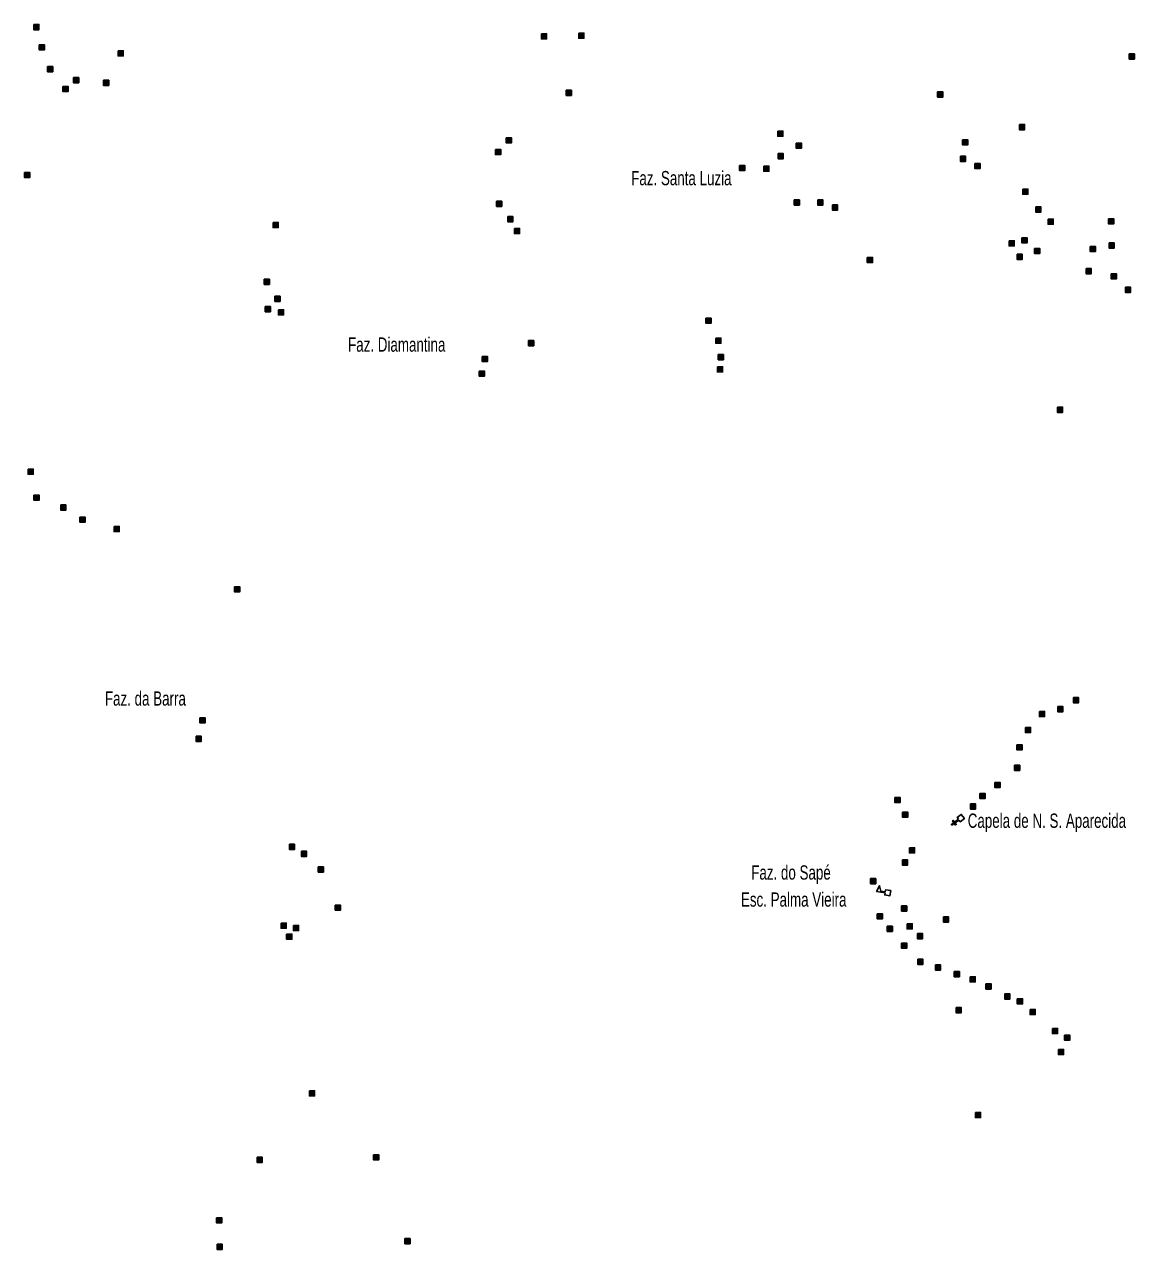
# Model space of a CAD drawing. Extents: x 265.7 to 292.1, y 7676.2 to 7704.2.
# Drawn here: x 279.63 to 285.84, y 7683.29 to 7690.15 of the extents above; entities that cross this region are included whole.
import ezdxf

# ---------------------------------------------------------------- set-up
doc = ezdxf.new("R2010")
doc.units = 0
doc.header["$LTSCALE"] = 0.032
for name, color, linetype, lineweight in [('2', 7, 'Continuous', 25), ('4', 7, 'Continuous', 25), ('6', 7, 'Continuous', 25)]:
    doc.layers.add(name, color=color, linetype=linetype, lineweight=lineweight)
doc.layers.add('61', color=7, linetype='Continuous')

msp = doc.modelspace()

# ---------------------------------------------------------------- hatches: boundary and pattern name
at = {"layer": '2'}
for points in [[(279.6791, 7690.1472), (279.7081, 7690.1472), (279.7081, 7690.1182), (279.6791, 7690.1182)], [(282.5223, 7690.0956), (282.5513, 7690.0956), (282.5513, 7690.0666), (282.5223, 7690.0666)], [(282.7314, 7690.0988), (282.7604, 7690.0988), (282.7604, 7690.0698), (282.7314, 7690.0698)], [(279.71, 7690.0341), (279.739, 7690.0341), (279.739, 7690.0051), (279.71, 7690.0051)], [(280.1511, 7690.0003), (280.1801, 7690.0003), (280.1801, 7689.9713), (280.1511, 7689.9713)], [(285.8142, 7689.9826), (285.8432, 7689.9826), (285.8432, 7689.9536), (285.8142, 7689.9536)], [(279.7565, 7689.9116), (279.7855, 7689.9116), (279.7855, 7689.8826), (279.7565, 7689.8826)], [(279.9019, 7689.8502), (279.9309, 7689.8502), (279.9309, 7689.8212), (279.9019, 7689.8212)], [(280.0698, 7689.8349), (280.0988, 7689.8349), (280.0988, 7689.8059), (280.0698, 7689.8059)], [(279.8429, 7689.8002), (279.8719, 7689.8002), (279.8719, 7689.7712), (279.8429, 7689.7712)], [(282.6612, 7689.7793), (282.6902, 7689.7793), (282.6902, 7689.7503), (282.6612, 7689.7503)], [(284.741, 7689.7695), (284.77, 7689.7695), (284.77, 7689.7405), (284.741, 7689.7405)], [(283.8451, 7689.5501), (283.8741, 7689.5501), (283.8741, 7689.5211), (283.8451, 7689.5211)], [(285.1986, 7689.5871), (285.2276, 7689.5871), (285.2276, 7689.5581), (285.1986, 7689.5581)], [(282.3247, 7689.5129), (282.3537, 7689.5129), (282.3537, 7689.4839), (282.3247, 7689.4839)], [(283.9493, 7689.483), (283.9783, 7689.483), (283.9783, 7689.454), (283.9493, 7689.454)], [(284.8807, 7689.5016), (284.9097, 7689.5016), (284.9097, 7689.4726), (284.8807, 7689.4726)], [(282.2649, 7689.4475), (282.2939, 7689.4475), (282.2939, 7689.4185), (282.2649, 7689.4185)], [(283.8476, 7689.4242), (283.8766, 7689.4242), (283.8766, 7689.3952), (283.8476, 7689.3952)], [(284.8684, 7689.4095), (284.8974, 7689.4095), (284.8974, 7689.3805), (284.8684, 7689.3805)], [(283.6321, 7689.3579), (283.6611, 7689.3579), (283.6611, 7689.3289), (283.6321, 7689.3289)], [(283.7668, 7689.3539), (283.7958, 7689.3539), (283.7958, 7689.3249), (283.7668, 7689.3249)], [(284.95, 7689.3692), (284.979, 7689.3692), (284.979, 7689.3402), (284.95, 7689.3402)], [(279.6275, 7689.3184), (279.6565, 7689.3184), (279.6565, 7689.2894), (279.6275, 7689.2894)], [(285.2172, 7689.2256), (285.2462, 7689.2256), (285.2462, 7689.1966), (285.2172, 7689.1966)], [(282.2714, 7689.1571), (282.3004, 7689.1571), (282.3004, 7689.1281), (282.2714, 7689.1281)], [(283.938, 7689.165), (283.967, 7689.165), (283.967, 7689.136), (283.938, 7689.136)], [(284.0694, 7689.1643), (284.0984, 7689.1643), (284.0984, 7689.1353), (284.0694, 7689.1353)], [(284.1518, 7689.1368), (284.1808, 7689.1368), (284.1808, 7689.1078), (284.1518, 7689.1078)], [(282.3335, 7689.0713), (282.3625, 7689.0713), (282.3625, 7689.0423), (282.3335, 7689.0423)], [(285.2905, 7689.1256), (285.3195, 7689.1256), (285.3195, 7689.0966), (285.2905, 7689.0966)], [(281.0197, 7689.0383), (281.0487, 7689.0383), (281.0487, 7689.0093), (281.0197, 7689.0093)], [(282.3705, 7689.0052), (282.3995, 7689.0052), (282.3995, 7688.9762), (282.3705, 7688.9762)], [(285.3591, 7689.0569), (285.3881, 7689.0569), (285.3881, 7689.0279), (285.3591, 7689.0279)], [(285.6982, 7689.0593), (285.7272, 7689.0593), (285.7272, 7689.0303), (285.6982, 7689.0303)], [(285.1412, 7688.9359), (285.1702, 7688.9359), (285.1702, 7688.9069), (285.1412, 7688.9069)], [(285.213, 7688.9528), (285.242, 7688.9528), (285.242, 7688.9238), (285.213, 7688.9238)], [(285.1855, 7688.8607), (285.2145, 7688.8607), (285.2145, 7688.8317), (285.1855, 7688.8317)], [(285.2833, 7688.893), (285.3123, 7688.893), (285.3123, 7688.864), (285.2833, 7688.864)], [(285.5956, 7688.9043), (285.6246, 7688.9043), (285.6246, 7688.8753), (285.5956, 7688.8753)], [(285.7013, 7688.9237), (285.7303, 7688.9237), (285.7303, 7688.8947), (285.7013, 7688.8947)], [(284.3471, 7688.843), (284.3761, 7688.843), (284.3761, 7688.814), (284.3471, 7688.814)], [(285.5721, 7688.7801), (285.6011, 7688.7801), (285.6011, 7688.7511), (285.5721, 7688.7511)], [(285.7126, 7688.751), (285.7416, 7688.751), (285.7416, 7688.722), (285.7126, 7688.722)], [(280.9697, 7688.7204), (280.9987, 7688.7204), (280.9987, 7688.6914), (280.9697, 7688.6914)], [(285.7926, 7688.6751), (285.8216, 7688.6751), (285.8216, 7688.6461), (285.7926, 7688.6461)], [(281.0294, 7688.6251), (281.0584, 7688.6251), (281.0584, 7688.5961), (281.0294, 7688.5961)], [(280.9752, 7688.567), (281.0042, 7688.567), (281.0042, 7688.538), (280.9752, 7688.538)], [(281.0496, 7688.5492), (281.0786, 7688.5492), (281.0786, 7688.5202), (281.0496, 7688.5202)], [(283.4431, 7688.5024), (283.4721, 7688.5024), (283.4721, 7688.4734), (283.4431, 7688.4734)], [(283.498, 7688.3911), (283.527, 7688.3911), (283.527, 7688.3621), (283.498, 7688.3621)], [(282.4505, 7688.3765), (282.4795, 7688.3765), (282.4795, 7688.3475), (282.4505, 7688.3475)], [(282.1907, 7688.2878), (282.2197, 7688.2878), (282.2197, 7688.2588), (282.1907, 7688.2588)], [(283.5126, 7688.2982), (283.5416, 7688.2982), (283.5416, 7688.2692), (283.5126, 7688.2692)], [(282.1737, 7688.2062), (282.2027, 7688.2062), (282.2027, 7688.1772), (282.1737, 7688.1772)], [(283.5078, 7688.2305), (283.5368, 7688.2305), (283.5368, 7688.2015), (283.5078, 7688.2015)], [(285.4116, 7688.0038), (285.4406, 7688.0038), (285.4406, 7687.9748), (285.4116, 7687.9748)], [(279.6476, 7687.6574), (279.6766, 7687.6574), (279.6766, 7687.6284), (279.6476, 7687.6284)], [(279.68, 7687.5114), (279.709, 7687.5114), (279.709, 7687.4824), (279.68, 7687.4824)], [(279.8308, 7687.4565), (279.8598, 7687.4565), (279.8598, 7687.4275), (279.8308, 7687.4275)], [(279.9374, 7687.3879), (279.9664, 7687.3879), (279.9664, 7687.3589), (279.9374, 7687.3589)], [(280.1295, 7687.3355), (280.1585, 7687.3355), (280.1585, 7687.3065), (280.1295, 7687.3065)], [(280.8042, 7686.998), (280.8332, 7686.998), (280.8332, 7686.969), (280.8042, 7686.969)], [(285.4132, 7686.3266), (285.4422, 7686.3266), (285.4422, 7686.2976), (285.4132, 7686.2976)], [(285.5012, 7686.3775), (285.5302, 7686.3775), (285.5302, 7686.3485), (285.5012, 7686.3485)], [(280.6096, 7686.2646), (280.6386, 7686.2646), (280.6386, 7686.2356), (280.6096, 7686.2356)], [(285.3107, 7686.3), (285.3397, 7686.3), (285.3397, 7686.271), (285.3107, 7686.271)], [(285.2325, 7686.2104), (285.2615, 7686.2104), (285.2615, 7686.1814), (285.2325, 7686.1814)], [(280.5879, 7686.1604), (280.6169, 7686.1604), (280.6169, 7686.1314), (280.5879, 7686.1314)], [(285.1848, 7686.1128), (285.2138, 7686.1128), (285.2138, 7686.0838), (285.1848, 7686.0838)], [(285.1719, 7685.9981), (285.2009, 7685.9981), (285.2009, 7685.9691), (285.1719, 7685.9691)], [(285.0614, 7685.9021), (285.0904, 7685.9021), (285.0904, 7685.8731), (285.0614, 7685.8731)], [(284.502, 7685.8181), (284.531, 7685.8181), (284.531, 7685.7891), (284.502, 7685.7891)], [(284.9241, 7685.7818), (284.9531, 7685.7818), (284.9531, 7685.7528), (284.9241, 7685.7528)], [(284.9774, 7685.84), (285.0064, 7685.84), (285.0064, 7685.811), (284.9774, 7685.811)], [(284.5448, 7685.7359), (284.5738, 7685.7359), (284.5738, 7685.7069), (284.5448, 7685.7069)], [(281.1109, 7685.5559), (281.1399, 7685.5559), (281.1399, 7685.5269), (281.1109, 7685.5269)], [(281.1778, 7685.5163), (281.2068, 7685.5163), (281.2068, 7685.4873), (281.1778, 7685.4873)], [(284.5827, 7685.5357), (284.6117, 7685.5357), (284.6117, 7685.5067), (284.5827, 7685.5067)], [(284.5432, 7685.4679), (284.5722, 7685.4679), (284.5722, 7685.4389), (284.5432, 7685.4389)], [(281.2723, 7685.4284), (281.3013, 7685.4284), (281.3013, 7685.3994), (281.2723, 7685.3994)], [(284.3657, 7685.363), (284.3947, 7685.363), (284.3947, 7685.334), (284.3657, 7685.334)], [(281.3675, 7685.2145), (281.3965, 7685.2145), (281.3965, 7685.1855), (281.3675, 7685.1855)], [(284.4028, 7685.166), (284.4318, 7685.166), (284.4318, 7685.137), (284.4028, 7685.137)], [(284.5392, 7685.2105), (284.5682, 7685.2105), (284.5682, 7685.1815), (284.5392, 7685.1815)], [(281.064, 7685.1144), (281.093, 7685.1144), (281.093, 7685.0854), (281.064, 7685.0854)], [(281.1334, 7685.1007), (281.1624, 7685.1007), (281.1624, 7685.0717), (281.1334, 7685.0717)], [(284.4585, 7685.0967), (284.4875, 7685.0967), (284.4875, 7685.0677), (284.4585, 7685.0677)], [(284.5698, 7685.1104), (284.5988, 7685.1104), (284.5988, 7685.0814), (284.5698, 7685.0814)], [(284.7732, 7685.1484), (284.8022, 7685.1484), (284.8022, 7685.1194), (284.7732, 7685.1194)], [(281.0955, 7685.0523), (281.1245, 7685.0523), (281.1245, 7685.0233), (281.0955, 7685.0233)], [(284.6279, 7685.0555), (284.6569, 7685.0555), (284.6569, 7685.0265), (284.6279, 7685.0265)], [(284.5392, 7685.0023), (284.5682, 7685.0023), (284.5682, 7684.9733), (284.5392, 7684.9733)], [(284.6296, 7684.9111), (284.6586, 7684.9111), (284.6586, 7684.8821), (284.6296, 7684.8821)], [(284.7281, 7684.8796), (284.7571, 7684.8796), (284.7571, 7684.8506), (284.7281, 7684.8506)], [(284.8337, 7684.8424), (284.8627, 7684.8424), (284.8627, 7684.8134), (284.8337, 7684.8134)], [(284.9226, 7684.8135), (284.9516, 7684.8135), (284.9516, 7684.7845), (284.9226, 7684.7845)], [(285.0113, 7684.7738), (285.0403, 7684.7738), (285.0403, 7684.7448), (285.0113, 7684.7448)], [(285.117, 7684.7174), (285.146, 7684.7174), (285.146, 7684.6884), (285.117, 7684.6884)], [(285.1871, 7684.69), (285.2161, 7684.69), (285.2161, 7684.661), (285.1871, 7684.661)], [(284.8442, 7684.6407), (284.8732, 7684.6407), (284.8732, 7684.6117), (284.8442, 7684.6117)], [(285.2583, 7684.6302), (285.2873, 7684.6302), (285.2873, 7684.6012), (285.2583, 7684.6012)], [(285.3833, 7684.5238), (285.4123, 7684.5238), (285.4123, 7684.4948), (285.3833, 7684.4948)], [(285.452, 7684.4866), (285.481, 7684.4866), (285.481, 7684.4576), (285.452, 7684.4576)], [(285.4172, 7684.4066), (285.4462, 7684.4066), (285.4462, 7684.3776), (285.4172, 7684.3776)], [(281.2229, 7684.1751), (281.2519, 7684.1751), (281.2519, 7684.1461), (281.2229, 7684.1461)], [(284.9523, 7684.0539), (284.9813, 7684.0539), (284.9813, 7684.0249), (284.9523, 7684.0249)], [(280.9301, 7683.8022), (280.9591, 7683.8022), (280.9591, 7683.7732), (280.9301, 7683.7732)], [(281.5822, 7683.8167), (281.6112, 7683.8167), (281.6112, 7683.7877), (281.5822, 7683.7877)], [(280.7034, 7683.4633), (280.7324, 7683.4633), (280.7324, 7683.4343), (280.7034, 7683.4343)], [(280.7057, 7683.3147), (280.7347, 7683.3147), (280.7347, 7683.2857), (280.7057, 7683.2857)], [(281.7581, 7683.3471), (281.7871, 7683.3471), (281.7871, 7683.3181), (281.7581, 7683.3181)]]:
    msp.add_hatch(color=256, dxfattribs=at).paths.add_polyline_path(points)

# ---------------------------------------------------------------- linework, layer by layer
for points in [[(279.6791, 7690.1472), (279.7081, 7690.1472), (279.7081, 7690.1182), (279.6791, 7690.1182)], [(282.5223, 7690.0956), (282.5513, 7690.0956), (282.5513, 7690.0666), (282.5223, 7690.0666)], [(282.7314, 7690.0988), (282.7604, 7690.0988), (282.7604, 7690.0698), (282.7314, 7690.0698)], [(279.71, 7690.0341), (279.739, 7690.0341), (279.739, 7690.0051), (279.71, 7690.0051)], [(280.1511, 7690.0003), (280.1801, 7690.0003), (280.1801, 7689.9713), (280.1511, 7689.9713)], [(285.8142, 7689.9826), (285.8432, 7689.9826), (285.8432, 7689.9536), (285.8142, 7689.9536)], [(279.7565, 7689.9116), (279.7855, 7689.9116), (279.7855, 7689.8826), (279.7565, 7689.8826)], [(279.9019, 7689.8502), (279.9309, 7689.8502), (279.9309, 7689.8212), (279.9019, 7689.8212)], [(280.0698, 7689.8349), (280.0988, 7689.8349), (280.0988, 7689.8059), (280.0698, 7689.8059)], [(279.8429, 7689.8002), (279.8719, 7689.8002), (279.8719, 7689.7712), (279.8429, 7689.7712)], [(282.6612, 7689.7793), (282.6902, 7689.7793), (282.6902, 7689.7503), (282.6612, 7689.7503)], [(284.741, 7689.7695), (284.77, 7689.7695), (284.77, 7689.7405), (284.741, 7689.7405)], [(283.8451, 7689.5501), (283.8741, 7689.5501), (283.8741, 7689.5211), (283.8451, 7689.5211)], [(285.1986, 7689.5871), (285.2276, 7689.5871), (285.2276, 7689.5581), (285.1986, 7689.5581)], [(282.3247, 7689.5129), (282.3537, 7689.5129), (282.3537, 7689.4839), (282.3247, 7689.4839)], [(283.9493, 7689.483), (283.9783, 7689.483), (283.9783, 7689.454), (283.9493, 7689.454)], [(284.8807, 7689.5016), (284.9097, 7689.5016), (284.9097, 7689.4726), (284.8807, 7689.4726)], [(282.2649, 7689.4475), (282.2939, 7689.4475), (282.2939, 7689.4185), (282.2649, 7689.4185)], [(283.8476, 7689.4242), (283.8766, 7689.4242), (283.8766, 7689.3952), (283.8476, 7689.3952)], [(284.8684, 7689.4095), (284.8974, 7689.4095), (284.8974, 7689.3805), (284.8684, 7689.3805)], [(283.6321, 7689.3579), (283.6611, 7689.3579), (283.6611, 7689.3289), (283.6321, 7689.3289)], [(283.7668, 7689.3539), (283.7958, 7689.3539), (283.7958, 7689.3249), (283.7668, 7689.3249)], [(284.95, 7689.3692), (284.979, 7689.3692), (284.979, 7689.3402), (284.95, 7689.3402)], [(279.6275, 7689.3184), (279.6565, 7689.3184), (279.6565, 7689.2894), (279.6275, 7689.2894)], [(285.2172, 7689.2256), (285.2462, 7689.2256), (285.2462, 7689.1966), (285.2172, 7689.1966)], [(282.2714, 7689.1571), (282.3004, 7689.1571), (282.3004, 7689.1281), (282.2714, 7689.1281)], [(283.938, 7689.165), (283.967, 7689.165), (283.967, 7689.136), (283.938, 7689.136)], [(284.0694, 7689.1643), (284.0984, 7689.1643), (284.0984, 7689.1353), (284.0694, 7689.1353)], [(284.1518, 7689.1368), (284.1808, 7689.1368), (284.1808, 7689.1078), (284.1518, 7689.1078)], [(282.3335, 7689.0713), (282.3625, 7689.0713), (282.3625, 7689.0423), (282.3335, 7689.0423)], [(285.2905, 7689.1256), (285.3195, 7689.1256), (285.3195, 7689.0966), (285.2905, 7689.0966)], [(281.0197, 7689.0383), (281.0487, 7689.0383), (281.0487, 7689.0093), (281.0197, 7689.0093)], [(282.3705, 7689.0052), (282.3995, 7689.0052), (282.3995, 7688.9762), (282.3705, 7688.9762)], [(285.3591, 7689.0569), (285.3881, 7689.0569), (285.3881, 7689.0279), (285.3591, 7689.0279)], [(285.6982, 7689.0593), (285.7272, 7689.0593), (285.7272, 7689.0303), (285.6982, 7689.0303)], [(285.1412, 7688.9359), (285.1702, 7688.9359), (285.1702, 7688.9069), (285.1412, 7688.9069)], [(285.213, 7688.9528), (285.242, 7688.9528), (285.242, 7688.9238), (285.213, 7688.9238)], [(285.1855, 7688.8607), (285.2145, 7688.8607), (285.2145, 7688.8317), (285.1855, 7688.8317)], [(285.2833, 7688.893), (285.3123, 7688.893), (285.3123, 7688.864), (285.2833, 7688.864)], [(285.5956, 7688.9043), (285.6246, 7688.9043), (285.6246, 7688.8753), (285.5956, 7688.8753)], [(285.7013, 7688.9237), (285.7303, 7688.9237), (285.7303, 7688.8947), (285.7013, 7688.8947)], [(284.3471, 7688.843), (284.3761, 7688.843), (284.3761, 7688.814), (284.3471, 7688.814)], [(285.5721, 7688.7801), (285.6011, 7688.7801), (285.6011, 7688.7511), (285.5721, 7688.7511)], [(285.7126, 7688.751), (285.7416, 7688.751), (285.7416, 7688.722), (285.7126, 7688.722)], [(280.9697, 7688.7204), (280.9987, 7688.7204), (280.9987, 7688.6914), (280.9697, 7688.6914)], [(285.7926, 7688.6751), (285.8216, 7688.6751), (285.8216, 7688.6461), (285.7926, 7688.6461)], [(281.0294, 7688.6251), (281.0584, 7688.6251), (281.0584, 7688.5961), (281.0294, 7688.5961)], [(280.9752, 7688.567), (281.0042, 7688.567), (281.0042, 7688.538), (280.9752, 7688.538)], [(281.0496, 7688.5492), (281.0786, 7688.5492), (281.0786, 7688.5202), (281.0496, 7688.5202)], [(283.4431, 7688.5024), (283.4721, 7688.5024), (283.4721, 7688.4734), (283.4431, 7688.4734)], [(283.498, 7688.3911), (283.527, 7688.3911), (283.527, 7688.3621), (283.498, 7688.3621)], [(282.4505, 7688.3765), (282.4795, 7688.3765), (282.4795, 7688.3475), (282.4505, 7688.3475)], [(282.1907, 7688.2878), (282.2197, 7688.2878), (282.2197, 7688.2588), (282.1907, 7688.2588)], [(283.5126, 7688.2982), (283.5416, 7688.2982), (283.5416, 7688.2692), (283.5126, 7688.2692)], [(282.1737, 7688.2062), (282.2027, 7688.2062), (282.2027, 7688.1772), (282.1737, 7688.1772)], [(283.5078, 7688.2305), (283.5368, 7688.2305), (283.5368, 7688.2015), (283.5078, 7688.2015)], [(285.4116, 7688.0038), (285.4406, 7688.0038), (285.4406, 7687.9748), (285.4116, 7687.9748)], [(279.6476, 7687.6574), (279.6766, 7687.6574), (279.6766, 7687.6284), (279.6476, 7687.6284)], [(279.68, 7687.5114), (279.709, 7687.5114), (279.709, 7687.4824), (279.68, 7687.4824)], [(279.8308, 7687.4565), (279.8598, 7687.4565), (279.8598, 7687.4275), (279.8308, 7687.4275)], [(279.9374, 7687.3879), (279.9664, 7687.3879), (279.9664, 7687.3589), (279.9374, 7687.3589)], [(280.1295, 7687.3355), (280.1585, 7687.3355), (280.1585, 7687.3065), (280.1295, 7687.3065)], [(280.8042, 7686.998), (280.8332, 7686.998), (280.8332, 7686.969), (280.8042, 7686.969)], [(285.4132, 7686.3266), (285.4422, 7686.3266), (285.4422, 7686.2976), (285.4132, 7686.2976)], [(285.5012, 7686.3775), (285.5302, 7686.3775), (285.5302, 7686.3485), (285.5012, 7686.3485)], [(280.6096, 7686.2646), (280.6386, 7686.2646), (280.6386, 7686.2356), (280.6096, 7686.2356)], [(285.3107, 7686.3), (285.3397, 7686.3), (285.3397, 7686.271), (285.3107, 7686.271)], [(285.2325, 7686.2104), (285.2615, 7686.2104), (285.2615, 7686.1814), (285.2325, 7686.1814)], [(280.5879, 7686.1604), (280.6169, 7686.1604), (280.6169, 7686.1314), (280.5879, 7686.1314)], [(285.1848, 7686.1128), (285.2138, 7686.1128), (285.2138, 7686.0838), (285.1848, 7686.0838)], [(285.1719, 7685.9981), (285.2009, 7685.9981), (285.2009, 7685.9691), (285.1719, 7685.9691)], [(285.0614, 7685.9021), (285.0904, 7685.9021), (285.0904, 7685.8731), (285.0614, 7685.8731)], [(284.502, 7685.8181), (284.531, 7685.8181), (284.531, 7685.7891), (284.502, 7685.7891)], [(284.9241, 7685.7818), (284.9531, 7685.7818), (284.9531, 7685.7528), (284.9241, 7685.7528)], [(284.9774, 7685.84), (285.0064, 7685.84), (285.0064, 7685.811), (284.9774, 7685.811)], [(284.5448, 7685.7359), (284.5738, 7685.7359), (284.5738, 7685.7069), (284.5448, 7685.7069)], [(281.1109, 7685.5559), (281.1399, 7685.5559), (281.1399, 7685.5269), (281.1109, 7685.5269)], [(281.1778, 7685.5163), (281.2068, 7685.5163), (281.2068, 7685.4873), (281.1778, 7685.4873)], [(284.5827, 7685.5357), (284.6117, 7685.5357), (284.6117, 7685.5067), (284.5827, 7685.5067)], [(284.5432, 7685.4679), (284.5722, 7685.4679), (284.5722, 7685.4389), (284.5432, 7685.4389)], [(281.2723, 7685.4284), (281.3013, 7685.4284), (281.3013, 7685.3994), (281.2723, 7685.3994)], [(284.3657, 7685.363), (284.3947, 7685.363), (284.3947, 7685.334), (284.3657, 7685.334)], [(281.3675, 7685.2145), (281.3965, 7685.2145), (281.3965, 7685.1855), (281.3675, 7685.1855)], [(284.4028, 7685.166), (284.4318, 7685.166), (284.4318, 7685.137), (284.4028, 7685.137)], [(284.5392, 7685.2105), (284.5682, 7685.2105), (284.5682, 7685.1815), (284.5392, 7685.1815)], [(281.064, 7685.1144), (281.093, 7685.1144), (281.093, 7685.0854), (281.064, 7685.0854)], [(281.1334, 7685.1007), (281.1624, 7685.1007), (281.1624, 7685.0717), (281.1334, 7685.0717)], [(284.4585, 7685.0967), (284.4875, 7685.0967), (284.4875, 7685.0677), (284.4585, 7685.0677)], [(284.5698, 7685.1104), (284.5988, 7685.1104), (284.5988, 7685.0814), (284.5698, 7685.0814)], [(284.7732, 7685.1484), (284.8022, 7685.1484), (284.8022, 7685.1194), (284.7732, 7685.1194)], [(281.0955, 7685.0523), (281.1245, 7685.0523), (281.1245, 7685.0233), (281.0955, 7685.0233)], [(284.6279, 7685.0555), (284.6569, 7685.0555), (284.6569, 7685.0265), (284.6279, 7685.0265)], [(284.5392, 7685.0023), (284.5682, 7685.0023), (284.5682, 7684.9733), (284.5392, 7684.9733)], [(284.6296, 7684.9111), (284.6586, 7684.9111), (284.6586, 7684.8821), (284.6296, 7684.8821)], [(284.7281, 7684.8796), (284.7571, 7684.8796), (284.7571, 7684.8506), (284.7281, 7684.8506)], [(284.8337, 7684.8424), (284.8627, 7684.8424), (284.8627, 7684.8134), (284.8337, 7684.8134)], [(284.9226, 7684.8135), (284.9516, 7684.8135), (284.9516, 7684.7845), (284.9226, 7684.7845)], [(285.0113, 7684.7738), (285.0403, 7684.7738), (285.0403, 7684.7448), (285.0113, 7684.7448)], [(285.117, 7684.7174), (285.146, 7684.7174), (285.146, 7684.6884), (285.117, 7684.6884)], [(285.1871, 7684.69), (285.2161, 7684.69), (285.2161, 7684.661), (285.1871, 7684.661)], [(284.8442, 7684.6407), (284.8732, 7684.6407), (284.8732, 7684.6117), (284.8442, 7684.6117)], [(285.2583, 7684.6302), (285.2873, 7684.6302), (285.2873, 7684.6012), (285.2583, 7684.6012)], [(285.3833, 7684.5238), (285.4123, 7684.5238), (285.4123, 7684.4948), (285.3833, 7684.4948)], [(285.452, 7684.4866), (285.481, 7684.4866), (285.481, 7684.4576), (285.452, 7684.4576)], [(285.4172, 7684.4066), (285.4462, 7684.4066), (285.4462, 7684.3776), (285.4172, 7684.3776)], [(281.2229, 7684.1751), (281.2519, 7684.1751), (281.2519, 7684.1461), (281.2229, 7684.1461)], [(284.9523, 7684.0539), (284.9813, 7684.0539), (284.9813, 7684.0249), (284.9523, 7684.0249)], [(280.9301, 7683.8022), (280.9591, 7683.8022), (280.9591, 7683.7732), (280.9301, 7683.7732)], [(281.5822, 7683.8167), (281.6112, 7683.8167), (281.6112, 7683.7877), (281.5822, 7683.7877)], [(280.7034, 7683.4633), (280.7324, 7683.4633), (280.7324, 7683.4343), (280.7034, 7683.4343)], [(280.7057, 7683.3147), (280.7347, 7683.3147), (280.7347, 7683.2857), (280.7057, 7683.2857)], [(281.7581, 7683.3471), (281.7871, 7683.3471), (281.7871, 7683.3181), (281.7581, 7683.3181)]]:
    msp.add_lwpolyline(points, close=True, dxfattribs=at)
at = {"layer": '4'}
for points in [[(284.447, 7685.2835), (284.3992, 7685.2911), (284.4159, 7685.3227), (284.422, 7685.2924), (284.4478, 7685.2884)], [(284.4478, 7685.2884), (284.4497, 7685.3003), (284.4783, 7685.2958), (284.4738, 7685.2672), (284.4451, 7685.2717), (284.447, 7685.2835)]]:
    msp.add_lwpolyline(points, dxfattribs=at)
at = {"layer": '6'}
for points in [[(284.8572, 7685.6953), (284.8501, 7685.7051), (284.8734, 7685.7223), (284.8906, 7685.699), (284.8673, 7685.6817), (284.86, 7685.6914)], [(284.86, 7685.6914), (284.8383, 7685.6753), (284.8455, 7685.6656), (284.8416, 7685.6627), (284.8343, 7685.6724), (284.8212, 7685.6627), (284.8183, 7685.6665), (284.8315, 7685.6763), (284.8243, 7685.686), (284.8282, 7685.6889), (284.8355, 7685.6792), (284.8572, 7685.6953)]]:
    msp.add_lwpolyline(points, dxfattribs=at)

# ---------------------------------------------------------------- texts
at = {"layer": '61', "width": 0.7}
for s, p in [('Faz. Santa Luzia', (283.0248, 7689.2469)), ('Faz. Diamantina', (281.4393, 7688.3145)), ('Faz. da Barra', (280.0776, 7686.3321)), ('Capela de N. S. Aparecida', (284.9094, 7685.6475)), ('Faz. do Sapé', (283.697, 7685.3575)), ('Esc. Palma Vieira', (283.6394, 7685.206))]:
    msp.add_text(s, height=0.08, dxfattribs=at).set_placement(p)

doc.saveas('drawing.dxf')
